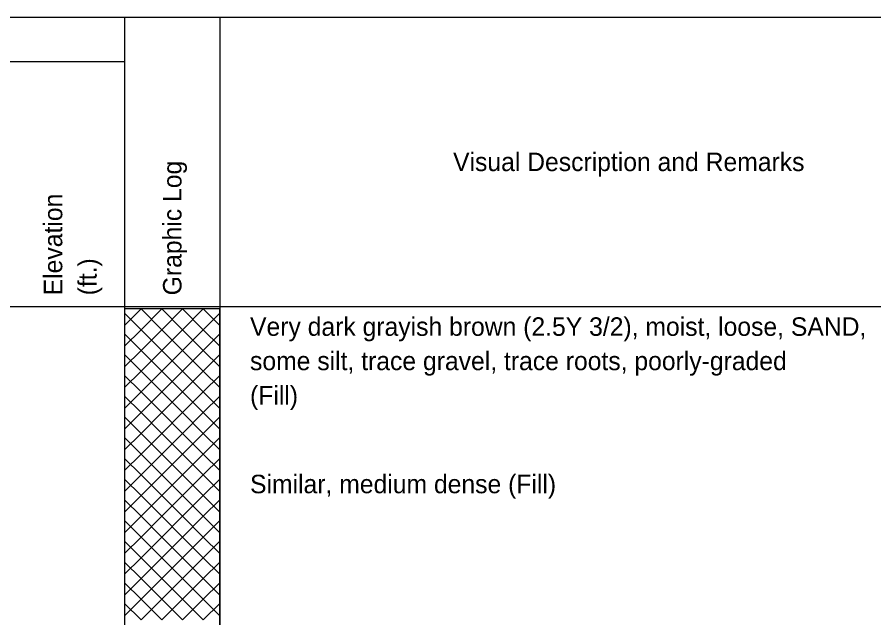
# Model space of a CAD drawing. Extents: x 9422 to 9552, y 6780 to 6860.
# Drawn here: x 9512.73 to 9523.06, y 6843.24 to 6850.49 of the extents above; entities that cross this region are included whole.
import ezdxf

# ---------------------------------------------------------------- set-up
doc = ezdxf.new("R2010")
doc.units = 0
doc.layers.add('7', color=7, linetype='Continuous')
doc.layers.add('8', color=7, linetype='Continuous')

msp = doc.modelspace()

# ---------------------------------------------------------------- linework, layer by layer
at = {"layer": '7'}
for p, q in [((9514.023, 6846.968), (9514.023, 6842.968)), ((9515.171, 6846.968), (9514.023, 6846.968)), ((9515.171, 6842.968), (9515.171, 6846.968))]:
    msp.add_line(p, q, dxfattribs=at)
for points in [[(9498.158, 6850.486), (9529.654, 6850.486)], [(9514.023, 6850.486), (9514.023, 6821.941)], [(9515.171, 6850.486), (9515.171, 6821.941)], [(9499.276, 6849.95), (9514.023, 6849.95)], [(9498.158, 6846.996), (9529.654, 6846.996)]]:
    msp.add_lwpolyline(points, dxfattribs=at)
at = {"layer": '8'}
for p, q in [((9514.023, 6846.769), (9514.222, 6846.968)), ((9514.472, 6846.718), (9514.222, 6846.968)), ((9514.222, 6846.718), (9514.472, 6846.968)), ((9514.722, 6846.718), (9514.472, 6846.968)), ((9514.472, 6846.718), (9514.722, 6846.968)), ((9514.972, 6846.718), (9514.722, 6846.968)), ((9514.722, 6846.718), (9514.972, 6846.968)), ((9515.171, 6846.769), (9514.972, 6846.968)), ((9514.222, 6846.718), (9514.023, 6846.917)), ((9514.972, 6846.718), (9515.171, 6846.917)), ((9514.023, 6846.519), (9514.222, 6846.718)), ((9514.222, 6846.468), (9514.023, 6846.667)), ((9514.472, 6846.468), (9514.222, 6846.718)), ((9514.222, 6846.468), (9514.472, 6846.718)), ((9514.722, 6846.468), (9514.472, 6846.718)), ((9514.472, 6846.468), (9514.722, 6846.718)), ((9514.972, 6846.468), (9514.722, 6846.718)), ((9514.722, 6846.468), (9514.972, 6846.718)), ((9515.171, 6846.519), (9514.972, 6846.718)), ((9514.972, 6846.468), (9515.171, 6846.667)), ((9514.023, 6846.269), (9514.222, 6846.468)), ((9514.222, 6846.218), (9514.023, 6846.417)), ((9514.472, 6846.218), (9514.222, 6846.468)), ((9514.222, 6846.218), (9514.472, 6846.468)), ((9514.722, 6846.218), (9514.472, 6846.468)), ((9514.472, 6846.218), (9514.722, 6846.468)), ((9514.972, 6846.218), (9514.722, 6846.468)), ((9514.722, 6846.218), (9514.972, 6846.468)), ((9515.171, 6846.269), (9514.972, 6846.468)), ((9514.972, 6846.218), (9515.171, 6846.417)), ((9514.023, 6846.019), (9514.222, 6846.218)), ((9514.472, 6845.968), (9514.222, 6846.218)), ((9514.222, 6845.968), (9514.472, 6846.218)), ((9514.722, 6845.968), (9514.472, 6846.218)), ((9514.472, 6845.968), (9514.722, 6846.218)), ((9514.972, 6845.968), (9514.722, 6846.218)), ((9514.722, 6845.968), (9514.972, 6846.218)), ((9515.171, 6846.019), (9514.972, 6846.218)), ((9514.222, 6845.968), (9514.023, 6846.167)), ((9514.972, 6845.968), (9515.171, 6846.167)), ((9514.023, 6845.769), (9514.222, 6845.968)), ((9514.222, 6845.718), (9514.023, 6845.917)), ((9514.472, 6845.718), (9514.222, 6845.968)), ((9514.222, 6845.718), (9514.472, 6845.968)), ((9514.722, 6845.718), (9514.472, 6845.968)), ((9514.472, 6845.718), (9514.722, 6845.968)), ((9514.972, 6845.718), (9514.722, 6845.968)), ((9514.722, 6845.718), (9514.972, 6845.968)), ((9515.171, 6845.769), (9514.972, 6845.968)), ((9514.972, 6845.718), (9515.171, 6845.917)), ((9514.023, 6845.519), (9514.222, 6845.718)), ((9514.472, 6845.468), (9514.222, 6845.718)), ((9514.222, 6845.468), (9514.472, 6845.718)), ((9514.722, 6845.468), (9514.472, 6845.718)), ((9514.472, 6845.468), (9514.722, 6845.718)), ((9514.972, 6845.468), (9514.722, 6845.718)), ((9514.722, 6845.468), (9514.972, 6845.718)), ((9515.171, 6845.519), (9514.972, 6845.718)), ((9514.222, 6845.468), (9514.023, 6845.667)), ((9514.972, 6845.468), (9515.171, 6845.667)), ((9514.023, 6845.269), (9514.222, 6845.468)), ((9514.222, 6845.218), (9514.023, 6845.417)), ((9514.472, 6845.218), (9514.222, 6845.468)), ((9514.222, 6845.218), (9514.472, 6845.468)), ((9514.722, 6845.218), (9514.472, 6845.468)), ((9514.472, 6845.218), (9514.722, 6845.468)), ((9514.972, 6845.218), (9514.722, 6845.468)), ((9514.722, 6845.218), (9514.972, 6845.468)), ((9515.171, 6845.269), (9514.972, 6845.468)), ((9514.972, 6845.218), (9515.171, 6845.417)), ((9514.023, 6845.019), (9514.222, 6845.218)), ((9514.472, 6844.968), (9514.222, 6845.218)), ((9514.222, 6844.968), (9514.472, 6845.218)), ((9514.722, 6844.968), (9514.472, 6845.218)), ((9514.472, 6844.968), (9514.722, 6845.218)), ((9514.972, 6844.968), (9514.722, 6845.218)), ((9514.722, 6844.968), (9514.972, 6845.218)), ((9515.171, 6845.019), (9514.972, 6845.218)), ((9514.222, 6844.968), (9514.023, 6845.167)), ((9514.972, 6844.968), (9515.171, 6845.167)), ((9514.023, 6844.769), (9514.222, 6844.968)), ((9514.472, 6844.718), (9514.222, 6844.968)), ((9514.222, 6844.718), (9514.472, 6844.968)), ((9514.722, 6844.718), (9514.472, 6844.968)), ((9514.472, 6844.718), (9514.722, 6844.968)), ((9514.972, 6844.718), (9514.722, 6844.968)), ((9514.722, 6844.718), (9514.972, 6844.968)), ((9515.171, 6844.769), (9514.972, 6844.968)), ((9514.222, 6844.718), (9514.023, 6844.917)), ((9514.972, 6844.718), (9515.171, 6844.917)), ((9514.023, 6844.519), (9514.222, 6844.718)), ((9514.222, 6844.468), (9514.023, 6844.667)), ((9514.472, 6844.468), (9514.222, 6844.718)), ((9514.222, 6844.468), (9514.472, 6844.718)), ((9514.722, 6844.468), (9514.472, 6844.718)), ((9514.472, 6844.468), (9514.722, 6844.718)), ((9514.972, 6844.468), (9514.722, 6844.718)), ((9514.722, 6844.468), (9514.972, 6844.718)), ((9515.171, 6844.519), (9514.972, 6844.718)), ((9514.972, 6844.468), (9515.171, 6844.667)), ((9514.023, 6844.269), (9514.222, 6844.468)), ((9514.472, 6844.218), (9514.222, 6844.468)), ((9514.222, 6844.218), (9514.472, 6844.468)), ((9514.722, 6844.218), (9514.472, 6844.468)), ((9514.472, 6844.218), (9514.722, 6844.468)), ((9514.972, 6844.218), (9514.722, 6844.468)), ((9514.722, 6844.218), (9514.972, 6844.468)), ((9515.171, 6844.269), (9514.972, 6844.468)), ((9514.222, 6844.218), (9514.023, 6844.418)), ((9514.972, 6844.218), (9515.171, 6844.418)), ((9514.023, 6844.019), (9514.222, 6844.218)), ((9514.222, 6843.968), (9514.023, 6844.168)), ((9514.472, 6843.968), (9514.222, 6844.218)), ((9514.222, 6843.968), (9514.472, 6844.218)), ((9514.722, 6843.968), (9514.472, 6844.218)), ((9514.472, 6843.968), (9514.722, 6844.218)), ((9514.972, 6843.968), (9514.722, 6844.218)), ((9514.722, 6843.968), (9514.972, 6844.218)), ((9515.171, 6844.019), (9514.972, 6844.218)), ((9514.972, 6843.968), (9515.171, 6844.168)), ((9514.023, 6843.769), (9514.222, 6843.968)), ((9514.472, 6843.718), (9514.222, 6843.968)), ((9514.222, 6843.718), (9514.472, 6843.968)), ((9514.722, 6843.718), (9514.472, 6843.968)), ((9514.472, 6843.718), (9514.722, 6843.968)), ((9514.972, 6843.718), (9514.722, 6843.968)), ((9514.722, 6843.718), (9514.972, 6843.968)), ((9515.171, 6843.769), (9514.972, 6843.968)), ((9514.222, 6843.718), (9514.023, 6843.917)), ((9514.972, 6843.718), (9515.171, 6843.917)), ((9514.023, 6843.519), (9514.222, 6843.718)), ((9514.222, 6843.468), (9514.023, 6843.668)), ((9514.472, 6843.468), (9514.222, 6843.718)), ((9514.222, 6843.468), (9514.472, 6843.718)), ((9514.722, 6843.468), (9514.472, 6843.718)), ((9514.472, 6843.468), (9514.722, 6843.718)), ((9514.972, 6843.468), (9514.722, 6843.718)), ((9514.722, 6843.468), (9514.972, 6843.718)), ((9515.171, 6843.519), (9514.972, 6843.718)), ((9514.972, 6843.468), (9515.171, 6843.668)), ((9514.023, 6843.269), (9514.222, 6843.468)), ((9514.222, 6843.218), (9514.023, 6843.418)), ((9514.472, 6843.218), (9514.222, 6843.468)), ((9514.222, 6843.218), (9514.472, 6843.468)), ((9514.722, 6843.218), (9514.472, 6843.468)), ((9514.472, 6843.218), (9514.722, 6843.468)), ((9514.972, 6843.218), (9514.722, 6843.468)), ((9514.722, 6843.218), (9514.972, 6843.468)), ((9515.171, 6843.269), (9514.972, 6843.468)), ((9514.972, 6843.218), (9515.171, 6843.418))]:
    msp.add_line(p, q, dxfattribs=at)

# ---------------------------------------------------------------- texts
at = {"layer": '7'}
for s, p in [('Visual Description and Remarks', (9517.985, 6848.63)), ('Very dark grayish brown (2.5Y 3/2), moist, loose, SAND,', (9515.536, 6846.644)), ('some silt, trace gravel, trace roots, poorly-graded', (9515.536, 6846.23)), ('(Fill)', (9515.536, 6845.816)), ('Similar, medium dense (Fill)', (9515.536, 6844.746))]:
    msp.add_text(s, height=0.2228, dxfattribs=at).set_placement(p)
for s, p in [('Graphic Log', (9514.709, 6847.132)), ('Elevation', (9513.271, 6847.132)), ('(ft.)', (9513.686, 6847.132))]:
    msp.add_text(s, height=0.2228, rotation=90, dxfattribs=at).set_placement(p)

doc.saveas('drawing.dxf')
